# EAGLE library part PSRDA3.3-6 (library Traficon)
DIODE ARRAY (ASD)
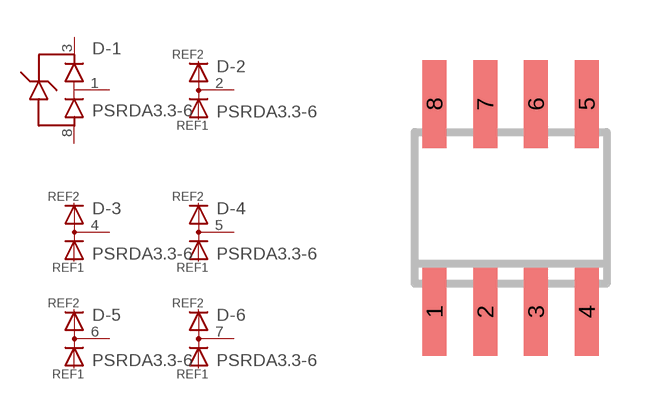
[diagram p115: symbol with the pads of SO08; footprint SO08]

Designator prefix D; gates -3=D-2-1 -4=D-2-1 -2=D-2-1 -5=D-2-1 -6=D-2-1 -1=REF

## PSRDA3.3-6  [SO08]
1  -1:IO
2  -2:K  pas
3  -1:VREF  pas
4  -3:K  pas
5  -4:K  pas
6  -5:K  pas
7  -6:K  pas
8  -1:GND  pas

## Footprint SO08 (pad centres in mm)
Small Outline Package
smd 0.6 x 2.2: 1 -1.905,-2.6; 2 -0.635,-2.6; 3 0.635,-2.6; 4 1.905,-2.6; 5 1.905,2.6; 6 0.635,2.6; 7 -0.635,2.6; 8 -1.905,2.6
